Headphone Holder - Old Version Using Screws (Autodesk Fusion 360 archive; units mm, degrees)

design "Headphone Holder" references "IKEA SKÅDIS"
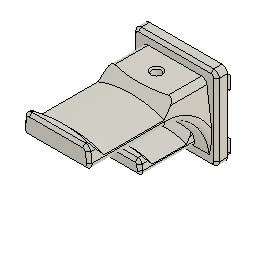
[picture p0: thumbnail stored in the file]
component_insert "Component Insert"
sketch "Sketch1" plane through (0, -5.4, 0) normal (0, -1, 0) x axis (1, 0, 0)
  line L1 (36.4, 44.9) -> (36.4, 35.1)
  line L2 (43.6, 35.1) -> (43.6, 44.9)
  line L3 (-43.6, 44.9) -> (-43.6, 35.1)
  line L4 (-36.4, 35.1) -> (-36.4, 44.9)
  line L5 (3.6, -44.9) -> (3.6, -35.1)
  line L6 (-3.6, -35.1) -> (-3.6, -44.9)
  line L7 (36.4, 4.9) -> (36.4, -4.9)
  line L8 (43.6, -4.9) -> (43.6, 4.9)
  line L9 (-43.6, 4.9) -> (-43.6, -4.9)
  line L10 (-36.4, -4.9) -> (-36.4, 4.9)
  line L11 (23.6, 15.1) -> (23.6, 24.9)
  line L12 (16.4, 24.9) -> (16.4, 15.1)
  line L13 (-16.4, -24.9) -> (-16.4, -15.1)
  line L14 (-23.6, -15.1) -> (-23.6, -24.9)
  line L15 (-16.4, 15.1) -> (-16.4, 24.9)
  line L16 (-23.6, 24.9) -> (-23.6, 15.1)
  line L17 (50, 52.5) -> (50, -52.5)
  line L18 (-50, 52.5) -> (50, 52.5)
  line L19 (-50, -52.5) -> (-50, 52.5)
  line L20 (50, -52.5) -> (-50, -52.5)
  line L21 (23.6, -24.9) -> (23.6, -15.1)
  line L22 (16.4, -15.1) -> (16.4, -24.9)
  line L23 (-3.6, 4.9) -> (-3.6, -4.9)
  line L24 (3.6, -4.9) -> (3.6, 4.9)
  line L25 (-36.4, -44.9) -> (-36.4, -35.1)
  line L26 (-43.6, -35.1) -> (-43.6, -44.9)
  line L27 (43.6, -44.9) -> (43.6, -35.1)
  line L28 (36.4, -35.1) -> (36.4, -44.9)
  line L29 (-3.6, 44.9) -> (-3.6, 35.1)
  line L30 (3.6, 35.1) -> (3.6, 44.9)
  line L31 (30.5, 30.5) -> (-30.5, 30.5)
  line L32 (30.5, -30.5) -> (30.5, 30.5)
  line L33 (-30.5, -30.5) -> (30.5, -30.5)
  line L34 (-30.5, 30.5) -> (-30.5, -30.5)
  line L35 (30.5, -30.5) -> (-30.5, 30.5)
  line L36 (36.4, 44.9) -> (36.4, 35.1)
  line L37 (43.6, 35.1) -> (43.6, 44.9)
  line L38 (-43.6, 44.9) -> (-43.6, 35.1)
  line L39 (-36.4, 35.1) -> (-36.4, 44.9)
  line L40 (3.6, -44.9) -> (3.6, -35.1)
  line L41 (-3.6, -35.1) -> (-3.6, -44.9)
  line L42 (36.4, 4.9) -> (36.4, -4.9)
  line L43 (43.6, -4.9) -> (43.6, 4.9)
  line L44 (-43.6, 4.9) -> (-43.6, -4.9)
  line L45 (-36.4, -4.9) -> (-36.4, 4.9)
  line L46 (23.6, 15.1) -> (23.6, 24.9)
  line L47 (16.4, 24.9) -> (16.4, 15.1)
  line L48 (-16.4, -24.9) -> (-16.4, -15.1)
  line L49 (-23.6, -15.1) -> (-23.6, -24.9)
  line L50 (-16.4, 15.1) -> (-16.4, 24.9)
  line L51 (-23.6, 24.9) -> (-23.6, 15.1)
  line L52 (50, 52.5) -> (50, -52.5)
  line L53 (-50, 52.5) -> (50, 52.5)
  line L54 (-50, -52.5) -> (-50, 52.5)
  line L55 (50, -52.5) -> (-50, -52.5)
  line L56 (23.6, -24.9) -> (23.6, -15.1)
  line L57 (16.4, -15.1) -> (16.4, -24.9)
  line L58 (-3.6, 4.9) -> (-3.6, -4.9)
  line L59 (3.6, -4.9) -> (3.6, 4.9)
  line L60 (-36.4, -44.9) -> (-36.4, -35.1)
  line L61 (-43.6, -35.1) -> (-43.6, -44.9)
  line L62 (43.6, -44.9) -> (43.6, -35.1)
  line L63 (36.4, -35.1) -> (36.4, -44.9)
  line L64 (-3.6, 44.9) -> (-3.6, 35.1)
  line L65 (3.6, 35.1) -> (3.6, 44.9)
  line L66 (36.4, 44.9) -> (36.4, 35.1)
  line L67 (43.6, 35.1) -> (43.6, 44.9)
  line L68 (-43.6, 44.9) -> (-43.6, 35.1)
  line L69 (-36.4, 35.1) -> (-36.4, 44.9)
  line L70 (3.6, -44.9) -> (3.6, -35.1)
  line L71 (-3.6, -35.1) -> (-3.6, -44.9)
  line L72 (36.4, 4.9) -> (36.4, -4.9)
  line L73 (43.6, -4.9) -> (43.6, 4.9)
  line L74 (-43.6, 4.9) -> (-43.6, -4.9)
  line L75 (-36.4, -4.9) -> (-36.4, 4.9)
  line L76 (23.6, 15.1) -> (23.6, 24.9)
  line L77 (16.4, 24.9) -> (16.4, 15.1)
  line L78 (-16.4, -24.9) -> (-16.4, -15.1)
  line L79 (-23.6, -15.1) -> (-23.6, -24.9)
  line L80 (-16.4, 15.1) -> (-16.4, 24.9)
  line L81 (-23.6, 24.9) -> (-23.6, 15.1)
  line L82 (50, 52.5) -> (50, -52.5)
  line L83 (-50, 52.5) -> (50, 52.5)
  line L84 (-50, -52.5) -> (-50, 52.5)
  line L85 (50, -52.5) -> (-50, -52.5)
  line L86 (23.6, -24.9) -> (23.6, -15.1)
  line L87 (16.4, -15.1) -> (16.4, -24.9)
  line L88 (-3.6, 4.9) -> (-3.6, -4.9)
  line L89 (3.6, -4.9) -> (3.6, 4.9)
  line L90 (-36.4, -44.9) -> (-36.4, -35.1)
  line L91 (-43.6, -35.1) -> (-43.6, -44.9)
  line L92 (43.6, -44.9) -> (43.6, -35.1)
  line L93 (36.4, -35.1) -> (36.4, -44.9)
  line L94 (-3.6, 44.9) -> (-3.6, 35.1)
  line L95 (3.6, 35.1) -> (3.6, 44.9)
  arc A1 centre (40, 35.1) radius 3.6 clockwise from (43.6, 35.1) to (36.4, 35.1)
  arc A2 centre (40, 44.9) radius 3.6 clockwise from (36.4, 44.9) to (43.6, 44.9)
  arc A3 centre (-40, 35.1) radius 3.6 clockwise from (-36.4, 35.1) to (-43.6, 35.1)
  arc A4 centre (-40, 44.9) radius 3.6 clockwise from (-43.6, 44.9) to (-36.4, 44.9)
  arc A5 centre (0, -35.1) radius 3.6 clockwise from (-3.6, -35.1) to (3.6, -35.1)
  arc A6 centre (0, -44.9) radius 3.6 clockwise from (3.6, -44.9) to (-3.6, -44.9)
  arc A7 centre (40, -4.9) radius 3.6 clockwise from (43.6, -4.9) to (36.4, -4.9)
  arc A8 centre (40, 4.9) radius 3.6 clockwise from (36.4, 4.9) to (43.6, 4.9)
  arc A9 centre (-40, -4.9) radius 3.6 clockwise from (-36.4, -4.9) to (-43.6, -4.9)
  arc A10 centre (-40, 4.9) radius 3.6 clockwise from (-43.6, 4.9) to (-36.4, 4.9)
  arc A11 centre (20, 15.1) radius 3.6 clockwise from (23.6, 15.1) to (16.4, 15.1)
  arc A12 centre (20, 24.9) radius 3.6 clockwise from (16.4, 24.9) to (23.6, 24.9)
  arc A13 centre (-20, -15.1) radius 3.6 clockwise from (-23.6, -15.1) to (-16.4, -15.1)
  arc A14 centre (-20, -24.9) radius 3.6 clockwise from (-16.4, -24.9) to (-23.6, -24.9)
  arc A15 centre (-20, 24.9) radius 3.6 clockwise from (-23.6, 24.9) to (-16.4, 24.9)
  arc A16 centre (-20, 15.1) radius 3.6 clockwise from (-16.4, 15.1) to (-23.6, 15.1)
  arc A17 centre (20, -15.1) radius 3.6 clockwise from (16.4, -15.1) to (23.6, -15.1)
  arc A18 centre (20, -24.9) radius 3.6 clockwise from (23.6, -24.9) to (16.4, -24.9)
  arc A19 centre (0, -4.9) radius 3.6 clockwise from (3.6, -4.9) to (-3.6, -4.9)
  arc A20 centre (0, 4.9) radius 3.6 clockwise from (-3.6, 4.9) to (3.6, 4.9)
  arc A21 centre (-40, -35.1) radius 3.6 clockwise from (-43.6, -35.1) to (-36.4, -35.1)
  arc A22 centre (-40, -44.9) radius 3.6 clockwise from (-36.4, -44.9) to (-43.6, -44.9)
  arc A23 centre (40, -35.1) radius 3.6 clockwise from (36.4, -35.1) to (43.6, -35.1)
  arc A24 centre (40, -44.9) radius 3.6 clockwise from (43.6, -44.9) to (36.4, -44.9)
  arc A25 centre (0, 35.1) radius 3.6 clockwise from (3.6, 35.1) to (-3.6, 35.1)
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  point P1 (0, 0)
  horizontal L31
  vertical L32
  horizontal L33
  vertical L34
  midpoint P1 L35
  equal L31 L34
  dimension "d27_1" distance A15 L31 = 2
extrude "Extrude1" new body sketch "Sketch1" profile of L11 A11 L12 A12 A13 L13 A14 L14 A15 L15 A16 L16 A17 L21 A18 L22 A19 L23 A20 L24 L31 L32 L33 L34 along normal blind 8 named "d31_1"
fillet "Fillet1" radius 4 named "d34_1"
sketch "Sketch2" plane through (0, -5.4, 0) normal (0, 1, 0) x axis (-1, 0, 0)
  line L1 (26.5, -30.5) -> (-26.5, -30.5)
  line L2 (30.5, 26.5) -> (30.5, -26.5)
  line L3 (-26.5, 30.5) -> (26.5, 30.5)
  line L4 (-30.5, -26.5) -> (-30.5, 26.5)
  line L5 (-22.4, 17.5) -> (-22.4, 15.1)
  line L6 (-17.6, 17.5) -> (-22.4, 17.5)
  line L7 (-17.6, 15.1) -> (-17.6, 17.5)
  arc A1 centre (-26.5, -26.5) radius 4 clockwise from (-26.5, -30.5) to (-30.5, -26.5)
  arc A2 centre (26.5, -26.5) radius 4 clockwise from (30.5, -26.5) to (26.5, -30.5)
  arc A3 centre (26.5, 26.5) radius 4 clockwise from (26.5, 30.5) to (30.5, 26.5)
  arc A4 centre (-26.5, 26.5) radius 4 clockwise from (-30.5, 26.5) to (-26.5, 30.5)
  arc A5 centre (-20, 15.1) radius 2.4 clockwise from (-17.6, 15.1) to (-22.4, 15.1)
  arc A6 centre (-20, 24.9) radius 2.6 clockwise from (-22.6, 24.9) to (-17.4, 24.9)
  arc A7 centre (-20, 15.1) radius 2.6 clockwise from (-17.4, 15.1) to (-22.6, 15.1)
  point P14 (-20, 15.1)
  point P24 (-20, 15.1)
  coincident P14 P24
  tangent A5 L5
  parallel L4 L5
  perpendicular L5 L6
  tangent A5 L7
  perpendicular L6 L7
  tangent A5 L6
  dimension "d38_1" distance A5 A7 = 0.2
extrude "Extrude2" add sketch "Sketch2" profile of A5 L5 L6 L7 along normal blind 5.4 named "d39_1"
sketch "Sketch3" plane through (0, 0, 0) normal (0, 1, 0) x axis (-1, 0, 0)
  line L1 (-17.6, 17.5) -> (-17.6, 15.1)
  line L2 (-22.4, 17.5) -> (-17.6, 17.5)
  line L3 (-22.4, 15.1) -> (-22.4, 17.5)
  line L4 (-22.4, 17.5) -> (-17.6, 17.5)
  line L5 (-22.4, 7.7) -> (-22.4, 17.5)
  line L6 (-17.6, 17.5) -> (-17.6, 7.7)
  line L7 (-17.4, 15.1) -> (-17.4, 24.9)
  arc A1 centre (-20, 15.1) radius 2.4 clockwise from (-17.6, 15.1) to (-22.4, 15.1)
  arc A2 centre (-20, 7.7) radius 2.4 clockwise from (-17.6, 7.7) to (-22.4, 7.7)
  point P5 (-17.6, 17.5)
  point P7 (-17.6, 17.5)
  point P6 (-22.4, 17.5)
  point P8 (-22.4, 17.5)
  point P9 (-22.4, 7.7)
  point P12 (-22.4, 7.7)
  horizontal L4
  vertical L5
  vertical L6
  coincident P5 P7
  coincident P6 P8
  equal L6 L7
  tangent L6 A2
  tangent L5 A2
  coincident P9 P12
extrude "Extrude3" add sketch "Sketch3" profile of A1 L1 L2 L3 L4 L5 L6 A2 along normal blind 5 named "d41_1"
fillet "Fillet2" radius 2.5 named "d44_1"
sketch "Sketch4" plane through (22.4, 0, 0) normal (1, 0, 0) x axis (0, 0, -1)
  line L1 (-17.5, -2.9) -> (-17.5, 2.5)
  line L2 (-15.1, -5.4) -> (-20, -5.4)
  line L3 (-15.1, 0) -> (-15.1, -5.4)
  line L4 (-7.7, 0) -> (-15.1, 0)
  line L5 (-7.7, 5) -> (-7.7, 0)
  line L6 (-15, 5) -> (-7.7, 5)
  line L7 (-4.7, 0.8038) -> (-7.7, 0)
  line L8 (-4.7, 0) -> (-4.7, 0.8038)
  line L9 (-7.7, 0) -> (-4.7, 0)
  arc A1 centre (-15, 2.5) radius 2.5 clockwise from (-17.5, 2.5) to (-15, 5)
  arc A2 centre (-20, -2.9) radius 2.5 clockwise from (-17.5, -2.9) to (-20, -5.4)
  point P10 (-7.7, 0)
  point P12 (-7.7, 0)
  point P14 (-4.7, 0)
  coincident P10 P12
  perpendicular L4 L8
  perpendicular L5 L9
  dimension "d45_1" angle L7 L9 = 15
  dimension "d46_1" distance P12 P14 = 3
extrude "Extrude4" cut sketch "Sketch4" profile of L7 L8 L9 no distance stored
rectangular_pattern "R-Pattern1" uSpaceDistance -40 named "d50_1" vSpaceDistance -40 named "d51_1"
sketch "Sketch5" plane through (0, -5.4, 0) normal (0, 1, 0) x axis (-1, 0, 0)
  line L1 (22.4, 20) -> (17.6, 20)
  line L2 (22.4, 15.1) -> (22.4, 20)
  line L3 (17.6, 20) -> (17.6, 15.1)
  line L4 (-17.6, 15.1) -> (-17.6, 20)
  line L5 (-22.4, 20) -> (-22.4, 15.1)
  line L6 (-17.6, 20) -> (-22.4, 20)
  line L7 (22.4, -20) -> (17.6, -20)
  line L8 (22.4, -24.9) -> (22.4, -20)
  line L9 (17.6, -20) -> (17.6, -24.9)
  line L10 (-17.6, -20) -> (-22.4, -20)
  line L11 (-17.6, -24.9) -> (-17.6, -20)
  line L12 (-22.4, -20) -> (-22.4, -24.9)
  line L13 (26.5, -30.5) -> (-26.5, -30.5)
  line L14 (30.5, 26.5) -> (30.5, -26.5)
  line L15 (-26.5, 30.5) -> (26.5, 30.5)
  line L16 (-30.5, -26.5) -> (-30.5, 26.5)
  line L17 (22.4, 27.3) -> (-22.4, 27.3)
  line L18 (22.4, -27.3) -> (22.4, 27.3)
  line L19 (-22.4, -27.3) -> (22.4, -27.3)
  line L20 (-22.4, 27.3) -> (-22.4, -27.3)
  line L21 (22.4, -27.3) -> (-22.4, 27.3)
  line L22 (-22.4, -27.3) -> (22.4, 27.3)
  arc A1 centre (20, 15.1) radius 2.4 clockwise from (22.4, 15.1) to (17.6, 15.1)
  arc A2 centre (-20, 15.1) radius 2.4 clockwise from (-17.6, 15.1) to (-22.4, 15.1)
  arc A3 centre (20, -24.9) radius 2.4 clockwise from (22.4, -24.9) to (17.6, -24.9)
  arc A4 centre (-20, -24.9) radius 2.4 clockwise from (-17.6, -24.9) to (-22.4, -24.9)
  arc A5 centre (-26.5, -26.5) radius 4 clockwise from (-26.5, -30.5) to (-30.5, -26.5)
  arc A6 centre (26.5, -26.5) radius 4 clockwise from (30.5, -26.5) to (26.5, -30.5)
  arc A7 centre (26.5, 26.5) radius 4 clockwise from (26.5, 30.5) to (30.5, 26.5)
  arc A8 centre (-26.5, 26.5) radius 4 clockwise from (-30.5, 26.5) to (-26.5, 30.5)
  point P38 (0, 0)
  point P1 (0, 0)
  horizontal L17
  perpendicular L17 L18
  parallel L17 L19
  parallel L18 L20
  coincident L21 P38
  coincident L22 P38
  coincident P1 P38
  tangent A3 L19
  tangent A3 L18
extrude "Extrude9" new body sketch "Sketch5" profile of L1 L2 A1 L3 L4 A2 L5 L6 L7 L8 A3 L9 L10 L11 A4 L12 L17 L18 L19 L20 against normal blind 5 bodies "Part Cutter"
sketch "Sketch11" plane through (0, -5.4, 0) normal (0, 1, 0) x axis (-1, 0, 0)
  line L1 (22.4, -27.3) -> (-22.4, -27.3)
  line L2 (22.4, 27.3) -> (22.4, -27.3)
  line L3 (-22.4, 27.3) -> (22.4, 27.3)
  line L4 (-22.4, -27.3) -> (-22.4, 27.3)
  circle C1 centre (0, 0) radius 45
  point P1 (0, 0)
  point P6 (0, 0)
  coincident P1 P6
  dimension "d150" diameter C1 = 90
extrude "Extrude10" add sketch "Sketch11" along normal blind 15
sketch "Sketch7" plane through (0, 0, 27.3) normal (0, 0, 1) x axis (1, 0, 0)
  line L1 (-22.4, -5.4) -> (22.4, -5.4)
  line L2 (-22.4, -10.4) -> (-22.4, -5.4)
  line L3 (22.4, -10.4) -> (-22.4, -10.4)
  line L4 (22.4, -5.4) -> (22.4, -10.4)
  line L5 (-27.4, -10.4) -> (-22.4, -5.4)
  line L6 (-22.4, -10.4) -> (-27.4, -10.4)
  line L7 (27.4, -10.4) -> (22.4, -5.4)
  line L8 (22.4, -10.4) -> (27.4, -10.4)
  point P3 (-22.4, -5.4)
  point P6 (-22.4, -5.4)
  point P4 (-22.4, -10.4)
  point P8 (-22.4, -10.4)
  point P2 (22.4, -5.4)
  point P9 (22.4, -5.4)
  point P5 (22.4, -10.4)
  point P11 (22.4, -10.4)
  coincident P3 P6
  coincident P4 P8
  coincident P2 P9
  coincident P5 P11
  perpendicular L4 L8
  perpendicular L2 L6
  equal L2 L6
  equal L4 L8
extrude "Extrude11" add sketch "Sketch7" profile of L2 L4 L5 L6 L7 L8 to an object
combine "Combine1" bodies "Mount Left Hook"
work_plane "WorkPlane1" AlongDistance 0
work_plane "WorkPlane2" AlongDistance 0
split "Split1" bodies "Mount Right Hook", "Mount Middle Part"
extrude "Extrude2" cut of existing geometry blind -0.2
offset_faces "OffsetFaces1" distance -0.2
sketch "Sketch3" plane through (17.6, 0, 0) normal (-1, 0, 0) x axis (0, 0, 1)
  line L1 (17.5, 2.5) -> (17.5, -2.9)
  line L2 (7.7, 5) -> (15, 5)
  line L3 (7.7, 0) -> (7.7, 5)
  line L4 (15.1, 0) -> (7.7, 0)
  line L5 (15.1, -5.4) -> (15.1, 0)
  line L6 (-20, -5.4) -> (15.1, -5.4)
  line L7 (-22.5, 2.5) -> (-22.5, -2.9)
  line L8 (-32.3, 5) -> (-25, 5)
  line L9 (-32.3, 0) -> (-32.3, 5)
  line L10 (-24.9, 0) -> (-32.3, 0)
  line L11 (-24.9, -5.4) -> (-24.9, 0)
  line L12 (-27.3, -5.4) -> (-24.9, -5.4)
  line L13 (-27.3, -10.4) -> (-27.3, -5.4)
  line L14 (27.3, -10.4) -> (-27.3, -10.4)
  line L15 (27.3, -5.4) -> (27.3, -10.4)
  line L16 (20, -5.4) -> (27.3, -5.4)
  line L17 (-9.5, -7.9) -> (-12, -5.4)
  line L18 (9.5, -7.9) -> (-9.5, -7.9)
  line L19 (12, -5.4) -> (9.5, -7.9)
  line L20 (0, -7.9) -> (0, -10.4)
  arc A1 centre (15, 2.5) radius 2.5 clockwise from (15, 5) to (17.5, 2.5)
  arc A2 centre (-20, -2.9) radius 2.5 clockwise from (-20, -5.4) to (-22.5, -2.9)
  arc A3 centre (-25, 2.5) radius 2.5 clockwise from (-25, 5) to (-22.5, 2.5)
  arc A4 centre (20, -2.9) radius 2.5 clockwise from (20, -5.4) to (17.5, -2.9)
  point P26 (-12, -5.4)
  point P29 (12, -5.4)
  point P30 (0, -10.4)
  point P31 (0, -7.9)
  point P27 (-9.5, -7.9)
  coincident L6 P26
  parallel L6 L18
  coincident L6 P29
  midpoint L14 P30
  midpoint L18 P31
  vertical L20
  dimension "d163" angle L17 L18 = 135
  dimension "d164" angle L18 L19 = 135
  dimension "d165" distance P26 P29 = 24
  dimension "d166" distance P26 P27 = 2.5
extrude "Extrude3" cut sketch "Sketch3" profile of L6 L17 L18 L19 no distance stored
sketch "Sketch4" plane through (17.4, 0, 0) normal (1, 0, 0) x axis (0, 0, -1)
  line L1 (-27.3, -5.4) -> (27.3, -5.4)
  line L2 (-27.3, -10.4) -> (-27.3, -5.4)
  line L3 (27.3, -10.4) -> (-27.3, -10.4)
  line L4 (27.3, -5.4) -> (27.3, -10.4)
  line L5 (-12, -5.4) -> (-9.5, -7.9)
  line L6 (-9.5, -7.9) -> (9.5, -7.9)
  line L7 (9.5, -7.9) -> (12, -5.4)
  line L8 (9.4172, -7.7) -> (11.8586, -5.2586)
  line L9 (-9.4172, -7.7) -> (9.4172, -7.7)
  line L10 (-11.8586, -5.2586) -> (-9.4172, -7.7)
  line L11 (-9.5, -7.9) -> (9.5, -7.9)
  line L12 (9.5, -7.9) -> (12, -5.4)
  line L13 (-12, -5.4) -> (-9.5, -7.9)
  dimension "d168" = 0.2
extrude "Extrude4" add sketch "Sketch4" profile of L1 L8 L9 L10 to an object Side2Offset 0
sketch "Sketch8" plane through (0, -5.4, 0) normal (0, 1, 0) x axis (-1, 0, 0)
  line L1 (-17.4, -27.3) -> (-17.4, -11.7172)
  line L2 (17.4, -27.3) -> (-17.4, -27.3)
  line L3 (17.4, -11.7172) -> (17.4, -27.3)
  line L4 (22.4, -11.7172) -> (17.4, -11.7172)
  line L5 (22.4, 11.7172) -> (22.4, -11.7172)
  line L6 (17.4, 11.7172) -> (22.4, 11.7172)
  line L7 (17.4, 27.3) -> (17.4, 11.7172)
  line L8 (-17.4, 27.3) -> (17.4, 27.3)
  line L9 (-17.4, 11.7172) -> (-17.4, 27.3)
  line L10 (-22.4, 11.7172) -> (-17.4, 11.7172)
  line L11 (-22.4, -11.7172) -> (-22.4, 11.7172)
  line L12 (-17.4, -11.7172) -> (-22.4, -11.7172)
  line L13 (-22.4, 0) -> (22.4, 0)
  line L14 (0, 27.3) -> (0, -27.3)
  circle C1 centre (13.4, 0) radius 1.6
  circle C2 centre (13.4, 0) radius 3
  circle C3 centre (-13.4, 0) radius 1.6
  circle C4 centre (-13.4, 0) radius 3
  point P14 (22.4, 0)
  point P15 (-22.4, 0)
  point P16 (13.4, 0)
  point P18 (0, -27.3)
  point P19 (0, 27.3)
  midpoint L5 P14
  midpoint L11 P15
  coincident L13 P16
  concentric C1 C2
  midpoint L2 P18
  midpoint L8 P19
  symmetric C1 L14 C3
  symmetric C2 L14 C4
  dimension "d205" diameter C1 = 3.2
  dimension "d206" diameter C2 = 6
  dimension "d208" distance L5 C2 = 6
extrude "Extrude9" cut sketch "Sketch8" profile of C1 C3 no distance stored
extrude "Extrude6" cut sketch "Sketch8" profile of C1 C2 C3 C4 against normal blind 3
sketch "Sketch7" plane through (0, -8.4, 0) normal (0, 1, 0) x axis (-1, 0, 0)
  line L1 (-10.8623, 1.6) -> (-15.9377, 1.6)
  line L2 (-10.8623, -1.6) -> (-15.9377, -1.6)
  line L3 (-15, -1.6) -> (-15, 1.6)
  line L4 (-11.8, -1.6) -> (-11.8, 1.6)
  circle C1 centre (-13.4, 0) radius 1.6
  circle C2 centre (-13.4, 0) radius 3
  point P3 (-15.9377, 1.6)
  point P4 (-10.8623, 1.6)
  point P5 (-15.9377, -1.6)
  point P6 (-10.8623, -1.6)
  point P7 (-15, 1.6)
  point P8 (-15, -1.6)
  point P9 (-11.8, 1.6)
  point P10 (-11.8, -1.6)
  coincident C2 P3
  coincident C2 P4
  horizontal L1
  coincident C2 P5
  coincident C2 P6
  parallel L1 L2
  coincident L1 P7
  coincident L2 P8
  perpendicular L1 L3
  coincident L1 P9
  perpendicular L1 L4
  tangent C1 L1
  tangent C1 L2
  tangent C1 L3
  tangent C1 L4
  coincident L2 P10
extrude "Extrude10" cut sketch "Sketch7" profile of C1 L1 L2 L3 L4 against normal blind 0.4
extrude "Extrude11" cut sketch "Sketch7" profile of C2 L1 L2 L3 L4 against normal blind 0.2
mirror "Mirror2" mirrorStitchTolerance 0.1
combine "Combine3" bodies "Part Cutter"
offset_faces "OffsetFaces2" distance -0.2
sketch "Sketch11" plane through (0, -10.6, 0) normal (0, 1, 0) x axis (-1, 0, 0)
  line L1 (27.8828, -27.5) -> (-27.8828, -27.5)
  line L2 (27.8828, 27.5) -> (27.8828, -27.5)
  line L3 (-27.8828, 27.5) -> (27.8828, 27.5)
  line L4 (-27.8828, -27.5) -> (-27.8828, 27.5)
  circle C1 centre (13.4, 0) radius 1.6
  circle C2 centre (-13.4, 0) radius 1.6
  circle C3 centre (13.4, 0) radius 1.25
  circle C4 centre (-13.4, 0) radius 1.25
  concentric C1 C3
  concentric C2 C4
  equal C3 C4
  dimension "d220" diameter C3 = 2.5
extrude "Extrude13" cut sketch "Sketch11" profile of C3 C4 against normal blind 2
copy_paste_bodies "CopyPasteBodies3"
component_from_bodies "Body->Comp3"
sketch "Sketch1" plane through (0, -13.4, 0) normal (0, -1, 0) x axis (1, 0, 0)
  line L1 (25, 8.5) -> (-25, 8.5)
  line L2 (23.0252, 23.5) -> (25, 8.5)
  line L3 (-23.0252, 23.5) -> (23.0252, 23.5)
  line L4 (-25, 8.5) -> (-23.0252, 23.5)
  line L5 (0, 23.5) -> (0, 8.5)
  line L6 (-26.5, 30.5) -> (26.5, 30.5)
  line L7 (30.5, 26.5) -> (30.5, -26.5)
  line L8 (30.5, 26.5) -> (30.5, -26.5)
  line L9 (-26.5, 30.5) -> (26.5, 30.5)
  line L10 (-30.5, -26.5) -> (-30.5, 26.5)
  line L11 (26.5, -30.5) -> (-26.5, -30.5)
  line L12 (30.5, 26.5) -> (30.5, -26.5)
  line L13 (-26.5, 30.5) -> (26.5, 30.5)
  line L14 (-30.5, -26.5) -> (-30.5, 26.5)
  line L15 (26.5, -30.5) -> (-26.5, -30.5)
  arc A1 centre (0, -48.5) radius 67 clockwise from (-24.2832, 13.9446) to (24.2832, 13.9446)
  arc A2 centre (26.5, -26.5) radius 4 clockwise from (30.5, -26.5) to (26.5, -30.5)
  arc A3 centre (26.5, 26.5) radius 4 clockwise from (26.5, 30.5) to (30.5, 26.5)
  arc A4 centre (-26.5, 26.5) radius 4 clockwise from (-30.5, 26.5) to (-26.5, 30.5)
  arc A5 centre (-26.5, -26.5) radius 4 clockwise from (-26.5, -30.5) to (-30.5, -26.5)
  arc A6 centre (26.5, -26.5) radius 4 clockwise from (30.5, -26.5) to (26.5, -30.5)
  arc A7 centre (26.5, 26.5) radius 4 clockwise from (26.5, 30.5) to (30.5, 26.5)
  arc A8 centre (-26.5, 26.5) radius 4 clockwise from (-30.5, 26.5) to (-26.5, 30.5)
  arc A9 centre (-26.5, -26.5) radius 4 clockwise from (-26.5, -30.5) to (-30.5, -26.5)
  point P5 (0, 8.5)
  point P6 (0, 23.5)
  point P8 (24.2832, 13.9446)
  point P7 (0, -48.5)
  point P9 (-24.2832, 13.9446)
  point P11 (25, 8.5)
  point P2 (25, 8.5)
  point P1 (0, 0)
  point P10 (-25, 8.5)
  midpoint L1 P5
  midpoint L3 P6
  perpendicular L1 L5
  coincident L2 P8
  coincident L5 P7
  coincident L4 P9
  coincident L2 P11
  coincident P2 P11
  coincident P1 L5
  vertical L5
  dimension "d52" angle L2 L4 = 15
  dimension "d53" distance L1 L3 = 15
  dimension "d68" distance A1 L6 = 12
  dimension "d69" distance L3 A1 = 5
  dimension "d70" radius A1 = 67
  dimension "d99" distance P10 P11 = 50
extrude "Extrude6" add sketch "Sketch1" profile of L1 L2 L3 L4 along normal blind 87
fillet "Fillet14" radius 32
fillet "Fillet16" radius 4
chamfer "Chamfer6" distance 2
sketch "Sketch2" plane through (0, 0, 0) normal (1, 0, 0) x axis (0, 0, -1)
  line L1 (-18.5, -45.4) -> (-18.5, -89.4)
  line L2 (-28.5, -35.4) -> (-18.5, -45.4)
  line L3 (-28.5, -99.4) -> (-28.5, -35.4)
  line L4 (-18.5, -89.4) -> (-28.5, -99.4)
  line L5 (-18.5, -67.4) -> (-28.5, -67.4)
  line L6 (-23.5, -13.4) -> (-23.5, -98.4)
  line L7 (-23.5, -98.4) -> (-23.5, -13.4)
  point P2 (-18.5, -89.4)
  point P6 (-18.5, -89.4)
  point P7 (-23.5, -94.4)
  point P8 (-28.5, -67.4)
  point P9 (-18.5, -67.4)
  point P10 (-23.5, -40.4)
  point P3 (-18.5, -45.4)
  point P11 (-23.5, -98.4)
  coincident P2 P6
  coincident L4 P7
  midpoint L4 P7
  midpoint L3 P8
  midpoint L1 P9
  perpendicular L1 L5
  midpoint L2 P10
  coincident P7 L6
  parallel L3 L7
  parallel L1 L7
  dimension "d118" angle L2 L4 = 90
  dimension "d119" distance P2 P3 = 44
  dimension "d227" distance P7 P11 = 4
  dimension "d228" distance P2 P11 = 5
sketch "Sketch3" plane through (0, 0, 0) normal (0, 1, 0) x axis (1, 0, 0)
  line L1 (0, 48.5) -> (0, 0)
  circle C1 centre (0, 48.5) radius 67
  point P2 (0, -18.5)
  point P1 (0, 0)
  point P4 (0, 0)
  point P3 (0, 48.5)
  point P5 (0, 48.5)
  coincident P2 C1
  coincident P1 P4
  coincident P3 P5
  vertical L1
  dimension "d110" diameter C1 = 134 (= "( 67 * 2 ) * 1 mm")
sweep "Sweep1" sketch "Sketch2" TwistAngle 0 TaperAngle 0
extrude "Extrude1" of existing geometry blind -8
copy_paste_bodies "CopyPasteBodies4"
component_from_bodies "Body->Comp4"
sketch "Sketch1" plane through (0, -13.4, 0) normal (0, -1, 0) x axis (1, 0, 0)
  line L1 (-13.6835, -13.5) -> (-15, -23.5)
  line L2 (13.6835, -13.5) -> (-13.6835, -13.5)
  line L3 (15, -23.5) -> (13.6835, -13.5)
  line L4 (0, -13.5) -> (0, 0)
  line L5 (25.1784, -23.5) -> (20.4389, 8.5)
  line L6 (-20.4389, 8.5) -> (20.4389, 8.5)
  line L7 (-20.4389, 8.5) -> (-25.1784, -23.5)
  line L8 (25.1784, -23.5) -> (-25.1784, -23.5)
  line L9 (15, -23.5) -> (-15, -23.5)
  line L10 (0, -23.5) -> (0, -13.5)
  line L11 (30.5, 26.5) -> (30.5, -26.5)
  line L12 (-26.5, 30.5) -> (26.5, 30.5)
  line L13 (-30.5, -26.5) -> (-30.5, 26.5)
  line L14 (26.5, -30.5) -> (-26.5, -30.5)
  line L15 (-23.4831, 20.0221) -> (-26.9729, -6.4855)
  line L16 (19.5173, 23.5) -> (-19.5173, 23.5)
  line L17 (26.9729, -6.4855) -> (23.4831, 20.0221)
  curve K1 (25.1784, -23.5) -> (26.9729, -6.4855)
  line L18 (-25.1784, -23.5) -> (25.1784, -23.5)
  curve K2 (-26.9729, -6.4855) -> (-25.1784, -23.5)
  line L19 (28.5, 26.5) -> (28.5, -26.5)
  line L20 (-26.5, 28.5) -> (26.5, 28.5)
  line L21 (-28.5, -26.5) -> (-28.5, 26.5)
  line L22 (26.5, -28.5) -> (-26.5, -28.5)
  arc A1 centre (26.5, -26.5) radius 4 clockwise from (30.5, -26.5) to (26.5, -30.5)
  arc A2 centre (26.5, 26.5) radius 4 clockwise from (26.5, 30.5) to (30.5, 26.5)
  arc A3 centre (-26.5, 26.5) radius 4 clockwise from (-30.5, 26.5) to (-26.5, 30.5)
  arc A4 centre (-26.5, -26.5) radius 4 clockwise from (-26.5, -30.5) to (-30.5, -26.5)
  arc A5 centre (-19.5173, 19.5) radius 4 clockwise from (-23.4831, 20.0221) to (-19.5173, 23.5)
  arc A6 centre (19.5173, 19.5) radius 4 clockwise from (19.5173, 23.5) to (23.4831, 20.0221)
  arc A7 centre (26.5, -26.5) radius 2 clockwise from (28.5, -26.5) to (26.5, -28.5)
  arc A8 centre (26.5, 26.5) radius 2 clockwise from (26.5, 28.5) to (28.5, 26.5)
  arc A9 centre (-26.5, 26.5) radius 2 clockwise from (-28.5, 26.5) to (-26.5, 28.5)
  arc A10 centre (-26.5, -26.5) radius 2 clockwise from (-26.5, -28.5) to (-28.5, -26.5)
  point P1 (0, 0)
  point P6 (0, 0)
  point P7 (0, -13.5)
  point P2 (-15, -23.5)
  point P5 (15, -23.5)
  point P12 (0, -23.5)
  coincident P1 P6
  midpoint L2 P7
  vertical L4
  coincident P2 L8
  coincident P5 L8
  equal L1 L3
  midpoint L9 P12
  vertical L10
  dimension "d145" angle L1 L3 = 15
  dimension "d146" distance P2 P5 = 30
  dimension "d147" distance L2 L9 = 10
extrude "Extrude8" new body sketch "Sketch1" profile of L1 L2 L3 L8 L9 L18 along normal blind 40 bodies "Cable Holder"
fillet "Fillet2" radius 3
chamfer "Chamfer1" distance 2
sketch "Sketch2" plane through (0, 0, 0) normal (1, 0, 0) x axis (0, 0, -1)
  line L1 (16.5, -44.4) -> (16.5, -19.4)
  line L2 (10.5, -50.4) -> (16.5, -44.4)
  line L3 (10.5, -13.4) -> (16.5, -19.4)
  line L4 (10.5, -50.4) -> (10.5, -13.4)
  line L5 (13.5, -13.4) -> (13.5, -51.4)
  line L6 (13.5, -51.4) -> (13.5, -13.4)
  point P5 (13.5, -47.4)
  point P4 (10.5, -50.4)
  point P8 (10.5, -50.4)
  point P9 (13.5, -16.4)
  point P10 (13.5, -51.4)
  point P2 (16.5, -19.4)
  point P3 (16.5, -44.4)
  coincident L2 P5
  vertical L1
  coincident P4 P8
  coincident L3 P9
  vertical L4
  midpoint L2 P5
  midpoint L3 P9
  coincident P5 L5
  dimension "d130" distance L1 P10 = 3
  dimension "d139" angle L2 L4 = 45
  dimension "d141" angle L3 L4 = 45
  dimension "d143" distance P2 P3 = 25
  dimension "d244" distance P5 P10 = 4
sketch "Sketch3" plane through (0, -53.4, 0) normal (0, -1, 0) x axis (1, 0, 0)
  line L1 (0, -54) -> (0, -16.5)
  line L2 (-12.5706, -20.3695) -> (-12.044, -16.3695)
  line L3 (11.5792, -21.5) -> (-11.5792, -21.5)
  line L4 (12.044, -16.3695) -> (12.5706, -20.3695)
  line L5 (-11.0525, -15.5) -> (11.0525, -15.5)
  circle C1 centre (0, -54) radius 37.5
  arc A1 centre (-11.0525, -16.5) radius 1 clockwise from (-12.044, -16.3695) to (-11.0525, -15.5)
  arc A2 centre (-11.5792, -20.5) radius 1 clockwise from (-11.5792, -21.5) to (-12.5706, -20.3695)
  arc A3 centre (11.5792, -20.5) radius 1 clockwise from (12.5706, -20.3695) to (11.5792, -21.5)
  arc A4 centre (11.0525, -16.5) radius 1 clockwise from (11.0525, -15.5) to (12.044, -16.3695)
  point P3 (0, -16.5)
  point P4 (0, -16.5)
  point P2 (0, -54)
  point P5 (0, -54)
  coincident C1 P3
  coincident P3 P4
  coincident P2 P5
  vertical L1
  dimension "d132" diameter C1 = 75
sweep "Sweep1" sketch "Sketch2" TwistAngle 0 TaperAngle 0
combine "Combine1" bodies "Cable Holder"
delete_face "DeleteFace3"
copy_paste_bodies "CopyPasteBodies5"
component_from_bodies "Body->Comp6"
sketch "Sketch1" plane through (0, 0, 23.5) normal (0, 0, 1) x axis (1, 0, 0)
  curve K1 (19.5173, -37.8016) -> (-19.5173, -37.8016)
  line L1 (19.5173, -13.4) -> (19.5173, -37.8016)
  line L2 (-19.5173, -13.4) -> (19.5173, -13.4)
  line L3 (-19.5173, -37.8016) -> (-19.5173, -13.4)
  line L4 (0, -40.4) -> (0, -13.4)
  circle C1 centre (0, -26.9) radius 3.35
  point P6 (0, -13.4)
  point P7 (0, -40.4)
  point P8 (0, -26.9)
  midpoint L2 P6
  coincident K1 P7
  perpendicular L2 L4
  midpoint L4 P8
  dimension "d252" diameter C1 = 6.7
extrude "Extrude1" cut sketch "Sketch1" profile of C1 against normal blind 25
chamfer "Chamfer1" distance 1
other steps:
base_feature "Base Feature1" bodies "Headphone Holder + Cable Hook + Adapter Hole"
base_feature "Base Feature3" bodies "Base Plate"
base_feature "Base Feature4" bodies "Headphone Holder", "Headphone Holder + Cable Hook"
base_feature "Base Feature5" bodies "Headphone Holder + Cable Hook", "Headphone Holder + Cable Hook + Adapter Hole"
base_feature "Base Feature1" bodies "Base Plate", "Headphone Holder"
base_feature "Base Feature1" bodies "Headphone Holder + Cable Hook"
create_component "CreateComponent2"
create_component "CreateComponent5"
create_component "CreateComponent8"
create_component "CreateComponent9"
remove_body "RemoveBody3"
create_component "CreateComponent10"
remove_body "RemoveBody4"
create_component "CreateComponent12"
remove_body "RemoveBody6"
named bodies: "Base Plate", "Part Cutter", "Mount Left Hook", "Mount Right Hook", "Mount Middle Part", "Headphone Holder", "Headphone Holder + Cable Hook", "Cable Holder", "Headphone Holder + Cable Hook + Adapter Hole"

design "IKEA SKÅDIS"
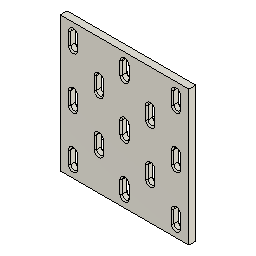
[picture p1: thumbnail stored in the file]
parameter "d27" = 2
parameter "d31" = 8
parameter "d32" = 0
parameter "d34" = 4
parameter "d38" = 0.2
parameter "d39" = 5.4
parameter "d40" = 0
parameter "d41" = 5
parameter "d42" = 0
parameter "d44" = 2.5
parameter "d45" = 15
parameter "d46" = 3
parameter "d47" = 0
parameter "d50" = -40
parameter "d51" = -40
parameter "d52" = 15
parameter "d53" = 15
parameter "d68" = 12
parameter "d69" = 5
parameter "d70" = 67
parameter "d71" = 0
parameter "d72" = 95
parameter "d73" = 0
parameter "d99" = 50
parameter "d101" = 32
parameter "d105" = 4
parameter "d106" = 2
parameter "d108" = 5
parameter "d110" = 134 (= "( 67 * 2 ) * 1 mm")
parameter "d115" = 0
parameter "d116" = 0
parameter "d117" = 4
parameter "d118" = 90
parameter "d119" = 44
parameter "d124" = 40
parameter "d125" = 0
parameter "d127" = 3
parameter "d128" = 2
parameter "d129" = 4
parameter "d130" = 3
parameter "d132" = 75
parameter "d137" = 0
parameter "d138" = 0
parameter "d139" = 45
parameter "d141" = 45
parameter "d142" = 4
parameter "d143" = 25
parameter "d144" = 3
parameter "d145" = 15
parameter "d146" = 30
parameter "d147" = 10
parameter "d148" = -5
parameter "d149" = 0
parameter "d150" = 90
parameter "d151" = 15
parameter "d152" = 0
parameter "d153" = -0.2
parameter "d158" = 0
parameter "d159" = 0
parameter "d160" = -0.2
parameter "d161" = 0
parameter "d162" = -0.2
parameter "d163" = 135
parameter "d164" = 135
parameter "d165" = 24
parameter "d166" = 2.5
parameter "d167" = 0
parameter "d168" = 0.2
parameter "d169" = 0
parameter "d170" = 0
parameter "d171" = 0
parameter "d172" = 0
parameter "d176" = -3
parameter "d177" = 0
parameter "d178" = 2.5
parameter "d179" = -8
parameter "d180" = 0
parameter "d188" = 0
parameter "d189" = 0
parameter "d205" = 3.2
parameter "d206" = 6
parameter "d207" = 0
parameter "d208" = 6
parameter "d209" = -0.4
parameter "d210" = 0
parameter "d211" = -0.2
parameter "d212" = 0
parameter "d214" = 0.1
parameter "d215" = 6.7
parameter "d216" = -25
parameter "d217" = 0
parameter "d218" = 1
sketch "Sketch1" plane through (0, 0, 0) normal (0, 1, 0) x axis (1, 0, 0)
  line L1 (2.6, 4.9) -> (2.6, -4.9)
  line L2 (-2.6, -4.9) -> (-2.6, 4.9)
  line L3 (0, 4.9) -> (0, -4.9)
  line L4 (22.6, -15.1) -> (22.6, -24.9)
  line L5 (17.4, -24.9) -> (17.4, -15.1)
  line L6 (20, -15.1) -> (20, -24.9)
  line L7 (2.6, 0) -> (-2.6, 0)
  line L8 (17.4, 24.9) -> (17.4, 15.1)
  line L9 (22.6, 15.1) -> (22.6, 24.9)
  line L10 (-17.4, -24.9) -> (-17.4, -15.1)
  line L11 (-22.6, -15.1) -> (-22.6, -24.9)
  line L12 (-22.6, 15.1) -> (-22.6, 24.9)
  line L13 (-17.4, 24.9) -> (-17.4, 15.1)
  line L14 (-50, 52.5) -> (50, 52.5)
  line L15 (-50, -52.5) -> (-50, 52.5)
  line L16 (50, -52.5) -> (-50, -52.5)
  line L17 (50, 52.5) -> (50, -52.5)
  line L18 (-50, -52.5) -> (50, 52.5)
  line L19 (50, -52.5) -> (-50, 52.5)
  arc A1 centre (0, 4.9) radius 2.6 clockwise from (-2.6, 4.9) to (2.6, 4.9)
  arc A2 centre (0, -4.9) radius 2.6 clockwise from (2.6, -4.9) to (-2.6, -4.9)
  arc A3 centre (20, -15.1) radius 2.6 clockwise from (17.4, -15.1) to (22.6, -15.1)
  arc A4 centre (20, -24.9) radius 2.6 clockwise from (22.6, -24.9) to (17.4, -24.9)
  arc A5 centre (20, 15.1) radius 2.6 clockwise from (22.6, 15.1) to (17.4, 15.1)
  arc A6 centre (20, 24.9) radius 2.6 clockwise from (17.4, 24.9) to (22.6, 24.9)
  arc A7 centre (-20, -24.9) radius 2.6 clockwise from (-17.4, -24.9) to (-22.6, -24.9)
  arc A8 centre (-20, -15.1) radius 2.6 clockwise from (-22.6, -15.1) to (-17.4, -15.1)
  arc A9 centre (-20, 15.1) radius 2.6 clockwise from (-17.4, 15.1) to (-22.6, 15.1)
  arc A10 centre (-20, 24.9) radius 2.6 clockwise from (-22.6, 24.9) to (-17.4, 24.9)
  point P1 (0, 0)
  point P8 (0, 0)
  point P15 (-2.6, 0)
  point P16 (2.6, 0)
  point P9 (22.6, -24.9)
  point P21 (22.6, 24.9)
  point P10 (22.6, -15.1)
  point P18 (22.6, 15.1)
  point P11 (17.4, -15.1)
  point P19 (17.4, 15.1)
  point P12 (17.4, -24.9)
  point P20 (17.4, 24.9)
  point P26 (-22.6, -24.9)
  point P27 (-22.6, -15.1)
  point P23 (-17.4, -15.1)
  point P24 (-17.4, -24.9)
  point P31 (-22.6, 15.1)
  point P30 (-17.4, 15.1)
  point P33 (-17.4, 24.9)
  point P32 (-22.6, 24.9)
  point P39 (0, 0)
  point P13 (20, -24.9)
  point P25 (-20, -24.9)
  point P35 (50, 52.5)
  point P36 (-50, 52.5)
  point P37 (-50, -52.5)
  tangent L1 A1
  tangent A1 L2
  parallel L1 L2
  tangent L2 A2
  tangent L1 A2
  vertical L3
  coincident P1 P8
  midpoint L3 P8
  tangent L4 A3
  tangent A3 L5
  parallel L4 L5
  tangent L5 A4
  tangent L4 A4
  vertical L6
  equal L2 L5
  equal A2 A4
  midpoint L2 P15
  midpoint L1 P16
  symmetric P9 L7 P21
  symmetric P10 L7 P18
  symmetric P11 L7 P19
  symmetric P12 L7 P20
  symmetric A3 L7 A5
  symmetric A4 L7 A6
  symmetric L3 P9 P26
  symmetric L3 P10 P27
  symmetric L3 P11 P23
  symmetric L3 P12 P24
  symmetric L3 A3 A8
  symmetric L3 A4 A7
  symmetric L3 P18 P31
  symmetric L3 P19 P30
  symmetric L3 A5 A9
  symmetric L3 P20 P33
  symmetric L3 P21 P32
  symmetric L3 A6 A10
  horizontal L14
  perpendicular L14 L15
  parallel L14 L16
  parallel L15 L17
  coincident L18 P39
  coincident L19 P39
  coincident P1 P39
  dimension "d1" = 15
  dimension "d2" distance L1 L2 = 5.2
  dimension "d8" distance P13 P25 = 40
  dimension "d9" distance A3 A5 = 25
  dimension "d16" distance P35 P36 = 100
  dimension "d17" distance P36 P37 = 105
extrude "Extrude1" new body sketch "Sketch1" profile of L1 A1 L2 A2 L4 A3 L5 A4 A5 L8 L9 A6 L10 A7 L11 A8 A9 L12 L13 A10 L14 L15 L16 L17 against normal blind 5.4
fillet "Fillet1" radius 1
rectangular_pattern "R-Pattern1" uSpaceDistance 40 vSpaceDistance 0
rectangular_pattern "R-Pattern2" uSpaceDistance 40 vSpaceDistance 0
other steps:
create_component "CreateComponent1"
